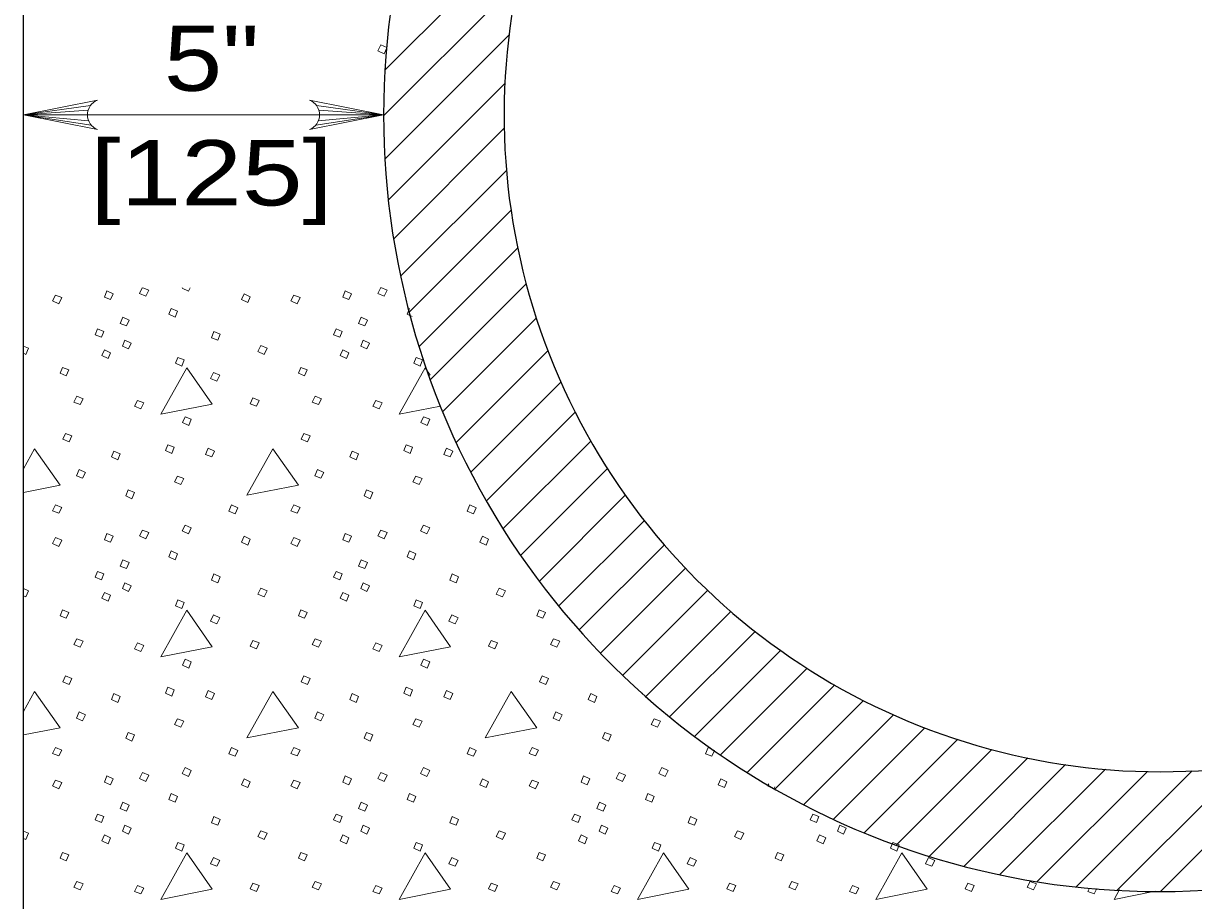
# Model space of a CAD drawing. Extents: x 1036.7 to 1070.7, y 883.9 to 905.9.
# Drawn here: x 1051.372 to 1054.169, y 894.74 to 896.836 of the extents above; entities that cross this region are included whole.
import ezdxf
from ezdxf.enums import TextEntityAlignment as Align

# ---------------------------------------------------------------- set-up
doc = ezdxf.new("R2010")
doc.units = 0
doc.header["$LTSCALE"] = 0.062
doc.layers.add('1', color=7, linetype='Continuous', lineweight=13)

msp = doc.modelspace()

# ---------------------------------------------------------------- linework, layer by layer
at = {"layer": '1'}
for p, q in [((1052.237, 896.72492), (1052.59142, 897.07925)), ((1052.23392, 896.61575), (1052.55467, 896.9365)), ((1052.23683, 896.51275), (1052.53375, 896.80967)), ((1052.22642, 896.78475), (1052.24092, 896.77892)), ((1052.245, 896.41483), (1052.5235, 896.69342)), ((1051.53242, 896.64), (1051.37217, 896.61758)), ((1051.527, 896.62892), (1051.37217, 896.61758)), ((1052.07292, 896.64), (1052.23317, 896.61758)), ((1052.07833, 896.62892), (1052.23317, 896.61758)), ((1052.07692, 896.61758), (1051.37217, 896.61758)), ((1051.52533, 896.61758), (1051.37217, 896.61758)), ((1051.52817, 896.60325), (1051.37217, 896.61758)), ((1051.53433, 896.59283), (1051.37217, 896.61758)), ((1052.23317, 896.61758), (1051.96858, 896.61758)), ((1052.071, 896.59283), (1052.23317, 896.61758)), ((1052.07717, 896.60325), (1052.23317, 896.61758)), ((1052.08, 896.61758), (1052.23317, 896.61758)), ((1052.25742, 896.32142), (1052.52175, 896.58567)), ((1052.27392, 896.23183), (1052.52692, 896.48475)), ((1052.29417, 896.14617), (1052.53792, 896.38975)), ((1052.31817, 896.06408), (1052.55392, 896.29983)), ((1052.34508, 895.985), (1052.57433, 896.21417)), ((1052.29533, 896.15517), (1052.29542, 896.15508)), ((1052.37467, 895.9085), (1052.59867, 896.1325)), ((1052.40667, 895.8345), (1052.62642, 896.05425)), ((1052.34467, 895.99567), (1052.33233, 896.01325)), ((1052.44175, 895.76358), (1052.65742, 895.97925)), ((1052.47942, 895.69525), (1052.69142, 895.90725)), ((1051.39875, 895.81933), (1051.37217, 895.77175)), ((1052.51917, 895.62892), (1052.72825, 895.83808)), ((1052.56083, 895.56467), (1052.76858, 895.77233)), ((1052.6055, 895.50333), (1052.81142, 895.70925)), ((1052.65225, 895.44408), (1052.85667, 895.6485)), ((1052.70075, 895.38658), (1052.90442, 895.59017)), ((1052.75158, 895.33133), (1052.95475, 895.5345)), ((1052.80483, 895.27867), (1053.008, 895.48175)), ((1052.86, 895.22775), (1053.06367, 895.43142)), ((1052.917, 895.17867), (1053.12167, 895.38333)), ((1052.97683, 895.13258), (1053.18192, 895.33758)), ((1053.03867, 895.08842), (1053.24558, 895.29533)), ((1051.39875, 895.23967), (1051.37217, 895.19208)), ((1053.1025, 895.04608), (1053.31175, 895.2555)), ((1053.16858, 895.00633), (1053.38067, 895.21833)), ((1053.23758, 894.96925), (1053.45233, 895.184)), ((1053.30875, 894.93442), (1053.527, 895.15267)), ((1053.38225, 894.90192), (1053.60533, 895.125)), ((1053.45858, 894.87217), (1053.68733, 895.101)), ((1053.53817, 894.84583), (1053.77325, 895.08083)), ((1053.62083, 894.82242), (1053.86333, 895.065)), ((1054.09, 894.7615), (1054.40967, 895.08117)), ((1053.7065, 894.80217), (1053.9585, 895.054)), ((1053.79583, 894.78542), (1054.05917, 895.04875)), ((1053.88908, 894.77267), (1054.16633, 895.04983)), ((1053.987, 894.7645), (1054.28267, 895.06017))]:
    msp.add_line(p, q, dxfattribs=at)
at = {"layer": '1', "lineweight": 25}
msp.add_lwpolyline([(1051.37217, 893.80992), (1051.37217, 899.32858), (1051.9695, 899.32858), (1051.9695, 900.49317)], dxfattribs=at)
at = {"layer": '1'}
for points in [[(1052.24092, 896.77775), (1052.23442, 896.76375), (1052.21942, 896.77075), (1052.22642, 896.78475)], [(1051.54917, 896.58225), (1051.37217, 896.61758), (1051.54917, 896.653)], [(1052.05617, 896.58225), (1052.23317, 896.61758), (1052.05617, 896.653)], [(1051.65792, 896.20458), (1051.67167, 896.19908), (1051.66467, 896.18408), (1051.64967, 896.19108), (1051.65642, 896.20458)], [(1051.77083, 896.20458), (1051.76658, 896.19608), (1051.75158, 896.20308), (1051.75233, 896.20458)], [(1052.3015, 896.1355), (1052.28933, 896.14117), (1052.29533, 896.15517)], [(1051.37217, 896.06517), (1051.38475, 896.06017), (1051.37775, 896.04517), (1051.37217, 896.04775)], [(1052.33233, 896.01325), (1052.27033, 895.90225), (1052.36958, 895.92158)], [(1051.37217, 895.71533), (1051.45975, 895.73242), (1051.39875, 895.81933)], [(1051.37217, 895.4855), (1051.38475, 895.4805), (1051.37775, 895.4655), (1051.37217, 895.46808)], [(1051.37217, 895.13567), (1051.45975, 895.15275), (1051.39875, 895.23967)], [(1052.85233, 895.23508), (1052.85108, 895.23567), (1052.85133, 895.23617)], [(1053.16817, 895.01167), (1053.16592, 895.00683), (1053.15092, 895.01383), (1053.15367, 895.01925)], [(1051.37217, 894.90583), (1051.38475, 894.90083), (1051.37775, 894.88583), (1051.37217, 894.88842)], [(1053.938, 894.76875), (1053.93158, 894.75592), (1053.91658, 894.76192), (1053.92042, 894.76958)], [(1053.99258, 894.76617), (1053.97958, 894.74292), (1054.07733, 894.76208)]]:
    msp.add_lwpolyline(points, dxfattribs=at)
for points in [[(1051.44875, 896.18708), (1051.46375, 896.18108), (1051.45675, 896.16617), (1051.44175, 896.17317)], [(1051.57167, 896.19708), (1051.58667, 896.19008), (1051.58067, 896.17617), (1051.56567, 896.18208)], [(1051.8995, 896.19008), (1051.9145, 896.18308), (1051.9085, 896.16917), (1051.8935, 896.17617)], [(1052.0185, 896.18708), (1052.0335, 896.18108), (1052.0265, 896.16617), (1052.0115, 896.17317)], [(1052.14142, 896.19708), (1052.15642, 896.19008), (1052.15042, 896.17617), (1052.13542, 896.18208)], [(1052.22642, 896.20508), (1052.24142, 896.19908), (1052.23442, 896.18408), (1052.21942, 896.19108)], [(1051.72558, 896.15517), (1051.74058, 896.14817), (1051.73458, 896.13417), (1051.71958, 896.14117)], [(1051.60967, 896.13417), (1051.62467, 896.12717), (1051.61867, 896.11317), (1051.60367, 896.11917)], [(1052.17942, 896.13417), (1052.19442, 896.12717), (1052.18842, 896.11317), (1052.17342, 896.11917)], [(1051.54967, 896.10617), (1051.56467, 896.10017), (1051.55867, 896.08617), (1051.54367, 896.09217)], [(1051.82758, 896.10017), (1051.84258, 896.09317), (1051.83658, 896.07917), (1051.82158, 896.08517)], [(1052.11942, 896.10617), (1052.13442, 896.10017), (1052.12842, 896.08617), (1052.11342, 896.09217)], [(1051.61467, 896.07917), (1051.62967, 896.07217), (1051.62367, 896.05817), (1051.60867, 896.06517)], [(1052.18442, 896.07917), (1052.19942, 896.07217), (1052.19342, 896.05817), (1052.17842, 896.06517)], [(1051.56567, 896.05617), (1051.58067, 896.04917), (1051.57467, 896.03517), (1051.55967, 896.04217)], [(1051.9395, 896.06617), (1051.9545, 896.06017), (1051.9475, 896.04517), (1051.9325, 896.05217)], [(1052.13542, 896.05617), (1052.15042, 896.04917), (1052.14442, 896.03517), (1052.12942, 896.04217)], [(1051.46575, 896.01425), (1051.48075, 896.00825), (1051.47475, 895.99425), (1051.45975, 896.00025)], [(1051.74158, 896.03817), (1051.75658, 896.03225), (1051.75058, 896.01725), (1051.73558, 896.02425)], [(1052.0355, 896.01425), (1052.0505, 896.00825), (1052.0445, 895.99425), (1052.0295, 896.00025)], [(1052.31133, 896.03817), (1052.32633, 896.03225), (1052.32033, 896.01725), (1052.30533, 896.02425)], [(1051.76258, 896.01325), (1051.70067, 895.90225), (1051.82358, 895.92625)], [(1051.82658, 896.00225), (1051.84158, 895.99525), (1051.83458, 895.98125), (1051.81958, 895.98725)], [(1051.49975, 895.94525), (1051.51475, 895.93925), (1051.50775, 895.92525), (1051.49275, 895.93125)], [(1051.64467, 895.93525), (1051.65967, 895.92925), (1051.65267, 895.91525), (1051.63767, 895.92125)], [(1051.9205, 895.94125), (1051.9355, 895.93525), (1051.9295, 895.92125), (1051.9145, 895.92725)], [(1052.0695, 895.94525), (1052.08442, 895.93925), (1052.07742, 895.92525), (1052.0625, 895.93125)], [(1052.21442, 895.93525), (1052.22942, 895.92925), (1052.22242, 895.91525), (1052.20742, 895.92125)], [(1051.75858, 895.89625), (1051.77358, 895.89033), (1051.76758, 895.87533), (1051.75258, 895.88233)], [(1052.32833, 895.89625), (1052.34333, 895.89033), (1052.33733, 895.87533), (1052.32233, 895.88233)], [(1051.47275, 895.85633), (1051.48775, 895.85033), (1051.48175, 895.83633), (1051.46675, 895.84233)], [(1052.0425, 895.85633), (1052.0575, 895.85033), (1052.0515, 895.83633), (1052.0365, 895.84233)], [(1051.71758, 895.82933), (1051.73258, 895.82333), (1051.72658, 895.80833), (1051.71167, 895.81533)], [(1051.81358, 895.82133), (1051.82858, 895.81433), (1051.82258, 895.80033), (1051.80758, 895.80633)], [(1051.9685, 895.81933), (1051.9065, 895.70842), (1052.0295, 895.73242)], [(1052.28733, 895.82933), (1052.30233, 895.82333), (1052.29633, 895.80833), (1052.28133, 895.81533)], [(1052.38333, 895.82133), (1052.39833, 895.81433), (1052.39233, 895.80033), (1052.37733, 895.80633)], [(1051.58867, 895.81433), (1051.60367, 895.80733), (1051.59767, 895.79333), (1051.58267, 895.80033)], [(1052.15842, 895.81433), (1052.17342, 895.80733), (1052.16742, 895.79333), (1052.15242, 895.80033)], [(1051.50575, 895.77033), (1051.52075, 895.76333), (1051.51375, 895.74933), (1051.49875, 895.75533)], [(1052.07542, 895.77033), (1052.09042, 895.76333), (1052.08342, 895.74933), (1052.0685, 895.75533)], [(1051.74058, 895.75433), (1051.75558, 895.74833), (1051.74858, 895.73442), (1051.73358, 895.74042)], [(1052.31033, 895.75433), (1052.32533, 895.74833), (1052.31833, 895.73442), (1052.30333, 895.74042)], [(1051.62267, 895.72142), (1051.63767, 895.71542), (1051.63167, 895.70042), (1051.61667, 895.70742)], [(1052.19242, 895.72142), (1052.20742, 895.71542), (1052.20142, 895.70042), (1052.18642, 895.70742)], [(1051.44875, 895.68542), (1051.46375, 895.67942), (1051.45675, 895.66542), (1051.44175, 895.67142)], [(1051.86958, 895.68542), (1051.88458, 895.67842), (1051.87858, 895.66442), (1051.86358, 895.67042)], [(1052.0185, 895.68542), (1052.0335, 895.67942), (1052.0265, 895.66542), (1052.0115, 895.67142)], [(1052.43925, 895.68542), (1052.45425, 895.67842), (1052.44825, 895.66442), (1052.43325, 895.67042)], [(1051.65667, 895.62542), (1051.67167, 895.61942), (1051.66467, 895.60442), (1051.64967, 895.61142)], [(1051.75858, 895.63742), (1051.77358, 895.63042), (1051.76658, 895.61642), (1051.75158, 895.62342)], [(1052.22642, 895.62542), (1052.24142, 895.61942), (1052.23442, 895.60442), (1052.21942, 895.61142)], [(1052.32833, 895.63742), (1052.34333, 895.63042), (1052.33633, 895.61642), (1052.32133, 895.62342)], [(1051.44875, 895.60742), (1051.46375, 895.60142), (1051.45675, 895.5865), (1051.44175, 895.5935)], [(1051.57167, 895.61742), (1051.58667, 895.61042), (1051.58067, 895.5965), (1051.56567, 895.60242)], [(1051.8995, 895.61042), (1051.9145, 895.60342), (1051.9085, 895.5895), (1051.8935, 895.5965)], [(1052.0185, 895.60742), (1052.0335, 895.60142), (1052.0265, 895.5865), (1052.0115, 895.5935)], [(1052.14142, 895.61742), (1052.15642, 895.61042), (1052.15042, 895.5965), (1052.13542, 895.60242)], [(1052.46925, 895.61042), (1052.48425, 895.60342), (1052.47825, 895.5895), (1052.46325, 895.5965)], [(1051.72558, 895.5755), (1051.74058, 895.5685), (1051.73458, 895.5545), (1051.71958, 895.5615)], [(1052.29533, 895.5755), (1052.31033, 895.5685), (1052.30433, 895.5545), (1052.28933, 895.5615)], [(1051.60967, 895.5545), (1051.62467, 895.5475), (1051.61867, 895.5335), (1051.60367, 895.5395)], [(1052.17942, 895.5545), (1052.19442, 895.5475), (1052.18842, 895.5335), (1052.17342, 895.5395)], [(1051.54967, 895.5265), (1051.56467, 895.5205), (1051.55867, 895.5065), (1051.54367, 895.5125)], [(1051.82758, 895.5205), (1051.84258, 895.5135), (1051.83658, 895.4995), (1051.82158, 895.5055)], [(1052.11942, 895.5265), (1052.13442, 895.5205), (1052.12842, 895.5065), (1052.11342, 895.5125)], [(1052.39733, 895.5205), (1052.41233, 895.5135), (1052.40633, 895.4995), (1052.39133, 895.5055)], [(1051.61467, 895.4995), (1051.62967, 895.4925), (1051.62367, 895.4785), (1051.60867, 895.4855)], [(1051.9395, 895.4865), (1051.9545, 895.4805), (1051.9475, 895.4655), (1051.9325, 895.4725)], [(1052.18442, 895.4995), (1052.19942, 895.4925), (1052.19342, 895.4785), (1052.17842, 895.4855)], [(1052.50925, 895.4865), (1052.52425, 895.4805), (1052.51725, 895.4655), (1052.50225, 895.4725)], [(1051.56567, 895.4765), (1051.58067, 895.4695), (1051.57467, 895.4555), (1051.55967, 895.4625)], [(1051.74158, 895.4585), (1051.75658, 895.45258), (1051.75058, 895.43758), (1051.73558, 895.44458)], [(1052.13542, 895.4765), (1052.15042, 895.4695), (1052.14442, 895.4555), (1052.12942, 895.4625)], [(1052.31133, 895.4585), (1052.32633, 895.45258), (1052.32033, 895.43758), (1052.30533, 895.44458)], [(1051.46575, 895.43458), (1051.48075, 895.42858), (1051.47475, 895.41458), (1051.45975, 895.42058)], [(1051.76258, 895.43358), (1051.70067, 895.32258), (1051.82358, 895.34658)], [(1052.0355, 895.43458), (1052.0505, 895.42858), (1052.0445, 895.41458), (1052.0295, 895.42058)], [(1052.33233, 895.43358), (1052.27033, 895.32258), (1052.39333, 895.34658)], [(1052.60517, 895.43458), (1052.62017, 895.42858), (1052.61417, 895.41458), (1052.59917, 895.42058)], [(1051.82658, 895.42258), (1051.84158, 895.41558), (1051.83458, 895.40158), (1051.81958, 895.40758)], [(1052.39633, 895.42258), (1052.41133, 895.41558), (1052.40433, 895.40158), (1052.38933, 895.40758)], [(1051.49975, 895.36558), (1051.51475, 895.35958), (1051.50775, 895.34558), (1051.49275, 895.35158)], [(1051.64467, 895.35558), (1051.65967, 895.34958), (1051.65267, 895.33558), (1051.63767, 895.34158)], [(1051.9205, 895.36158), (1051.9355, 895.35558), (1051.9295, 895.34158), (1051.9145, 895.34758)], [(1052.0695, 895.36558), (1052.08442, 895.35958), (1052.07742, 895.34558), (1052.0625, 895.35158)], [(1052.21442, 895.35558), (1052.22942, 895.34958), (1052.22242, 895.33558), (1052.20742, 895.34158)], [(1052.49025, 895.36158), (1052.50525, 895.35558), (1052.49925, 895.34158), (1052.48425, 895.34758)], [(1052.63917, 895.36558), (1052.65417, 895.35958), (1052.64717, 895.34558), (1052.63217, 895.35158)], [(1051.75858, 895.31658), (1051.77358, 895.31058), (1051.76758, 895.29567), (1051.75258, 895.30267)], [(1052.32833, 895.31658), (1052.34333, 895.31058), (1052.33733, 895.29567), (1052.32233, 895.30267)], [(1051.47275, 895.27667), (1051.48775, 895.27067), (1051.48175, 895.25667), (1051.46675, 895.26267)], [(1052.0425, 895.27667), (1052.0575, 895.27067), (1052.0515, 895.25667), (1052.0365, 895.26267)], [(1052.61217, 895.27667), (1052.62717, 895.27067), (1052.62117, 895.25667), (1052.60617, 895.26267)], [(1051.58867, 895.23467), (1051.60367, 895.22767), (1051.59767, 895.21367), (1051.58267, 895.22067)], [(1051.71758, 895.24967), (1051.73258, 895.24367), (1051.72658, 895.22867), (1051.71167, 895.23567)], [(1051.81358, 895.24167), (1051.82858, 895.23467), (1051.82258, 895.22067), (1051.80758, 895.22667)], [(1051.9685, 895.23967), (1051.9065, 895.12875), (1052.0295, 895.15275)], [(1052.15842, 895.23467), (1052.17342, 895.22767), (1052.16742, 895.21367), (1052.15242, 895.22067)], [(1052.28733, 895.24967), (1052.30233, 895.24367), (1052.29633, 895.22867), (1052.28133, 895.23567)], [(1052.38333, 895.24167), (1052.39833, 895.23467), (1052.39233, 895.22067), (1052.37733, 895.22667)], [(1052.53825, 895.23967), (1052.47625, 895.12875), (1052.59917, 895.15275)], [(1052.72817, 895.23467), (1052.74317, 895.22767), (1052.73717, 895.21367), (1052.72217, 895.22067)], [(1051.50575, 895.19067), (1051.52075, 895.18367), (1051.51375, 895.16967), (1051.49875, 895.17567)], [(1051.74058, 895.17467), (1051.75558, 895.16867), (1051.74858, 895.15475), (1051.73358, 895.16075)], [(1052.07542, 895.19067), (1052.09042, 895.18367), (1052.08342, 895.16967), (1052.0685, 895.17567)], [(1052.31033, 895.17467), (1052.32533, 895.16867), (1052.31833, 895.15475), (1052.30333, 895.16075)], [(1052.64517, 895.19067), (1052.66017, 895.18367), (1052.65317, 895.16967), (1052.63817, 895.17567)], [(1052.88008, 895.17467), (1052.89508, 895.16867), (1052.88808, 895.15475), (1052.87308, 895.16075)], [(1051.62267, 895.14175), (1051.63767, 895.13575), (1051.63167, 895.12075), (1051.61667, 895.12775)], [(1052.19242, 895.14175), (1052.20742, 895.13575), (1052.20142, 895.12075), (1052.18642, 895.12775)], [(1052.76217, 895.14175), (1052.77708, 895.13575), (1052.77117, 895.12075), (1052.75617, 895.12775)], [(1051.44875, 895.10575), (1051.46375, 895.09975), (1051.45675, 895.08575), (1051.44175, 895.09175)], [(1051.86958, 895.10575), (1051.88458, 895.09875), (1051.87858, 895.08475), (1051.86358, 895.09075)], [(1052.0185, 895.10575), (1052.0335, 895.09975), (1052.0265, 895.08575), (1052.0115, 895.09175)], [(1052.43925, 895.10575), (1052.45425, 895.09875), (1052.44825, 895.08475), (1052.43325, 895.09075)], [(1052.58825, 895.10575), (1052.60317, 895.09975), (1052.59625, 895.08575), (1052.58125, 895.09175)], [(1053.009, 895.10575), (1053.024, 895.09875), (1053.018, 895.08475), (1053.003, 895.09075)], [(1051.57167, 895.03775), (1051.58667, 895.03075), (1051.58067, 895.01683), (1051.56567, 895.02275)], [(1051.65667, 895.04575), (1051.67167, 895.03975), (1051.66467, 895.02475), (1051.64967, 895.03175)], [(1051.75858, 895.05775), (1051.77358, 895.05075), (1051.76658, 895.03675), (1051.75158, 895.04375)], [(1052.14142, 895.03775), (1052.15642, 895.03075), (1052.15042, 895.01683), (1052.13542, 895.02275)], [(1052.22642, 895.04575), (1052.24142, 895.03975), (1052.23442, 895.02475), (1052.21942, 895.03175)], [(1052.32833, 895.05775), (1052.34333, 895.05075), (1052.33633, 895.03675), (1052.32133, 895.04375)], [(1052.71117, 895.03775), (1052.72617, 895.03075), (1052.72017, 895.01683), (1052.70517, 895.02275)], [(1052.79608, 895.04575), (1052.81108, 895.03975), (1052.80408, 895.02475), (1052.78908, 895.03175)], [(1052.89808, 895.05775), (1052.91308, 895.05075), (1052.90608, 895.03675), (1052.89108, 895.04375)], [(1051.44875, 895.02775), (1051.46375, 895.02183), (1051.45675, 895.00683), (1051.44175, 895.01383)], [(1051.8995, 895.03075), (1051.9145, 895.02375), (1051.9085, 895.00983), (1051.8935, 895.01683)], [(1052.0185, 895.02775), (1052.0335, 895.02183), (1052.0265, 895.00683), (1052.0115, 895.01383)], [(1052.46925, 895.03075), (1052.48425, 895.02375), (1052.47825, 895.00983), (1052.46325, 895.01683)], [(1052.58825, 895.02775), (1052.60317, 895.02183), (1052.59625, 895.00683), (1052.58125, 895.01383)], [(1053.039, 895.03075), (1053.054, 895.02375), (1053.048, 895.00983), (1053.033, 895.01683)], [(1051.72558, 894.99583), (1051.74058, 894.98883), (1051.73458, 894.97483), (1051.71958, 894.98183)], [(1052.29533, 894.99583), (1052.31033, 894.98883), (1052.30433, 894.97483), (1052.28933, 894.98183)], [(1052.86508, 894.99583), (1052.88008, 894.98883), (1052.87408, 894.97483), (1052.85908, 894.98183)], [(1051.60967, 894.97483), (1051.62467, 894.96783), (1051.61867, 894.95383), (1051.60367, 894.95983)], [(1052.17942, 894.97483), (1052.19442, 894.96783), (1052.18842, 894.95383), (1052.17342, 894.95983)], [(1052.74917, 894.97483), (1052.76417, 894.96783), (1052.75817, 894.95383), (1052.74317, 894.95983)], [(1051.54967, 894.94683), (1051.56467, 894.94083), (1051.55867, 894.92683), (1051.54367, 894.93283)], [(1051.82758, 894.94083), (1051.84258, 894.93383), (1051.83658, 894.91983), (1051.82158, 894.92583)], [(1052.11942, 894.94683), (1052.13442, 894.94083), (1052.12842, 894.92683), (1052.11342, 894.93283)], [(1052.39733, 894.94083), (1052.41233, 894.93383), (1052.40633, 894.91983), (1052.39133, 894.92583)], [(1052.68917, 894.94683), (1052.70417, 894.94083), (1052.69817, 894.92683), (1052.68317, 894.93283)], [(1052.967, 894.94083), (1052.982, 894.93383), (1052.976, 894.91983), (1052.961, 894.92583)], [(1053.25892, 894.94683), (1053.27392, 894.94083), (1053.26792, 894.92683), (1053.25292, 894.93283)], [(1051.56567, 894.89683), (1051.58067, 894.88983), (1051.57467, 894.87583), (1051.55967, 894.88283)], [(1051.61467, 894.91983), (1051.62967, 894.91283), (1051.62367, 894.89883), (1051.60867, 894.90583)], [(1051.9395, 894.90683), (1051.9545, 894.90083), (1051.9475, 894.88583), (1051.9325, 894.89283)], [(1052.13542, 894.89683), (1052.15042, 894.88983), (1052.14442, 894.87583), (1052.12942, 894.88283)], [(1052.18442, 894.91983), (1052.19942, 894.91283), (1052.19342, 894.89883), (1052.17842, 894.90583)], [(1052.50925, 894.90683), (1052.52425, 894.90083), (1052.51725, 894.88583), (1052.50225, 894.89283)], [(1052.70517, 894.89683), (1052.72017, 894.88983), (1052.71417, 894.87583), (1052.69917, 894.88283)], [(1052.75417, 894.91983), (1052.76917, 894.91283), (1052.76317, 894.89883), (1052.74817, 894.90583)], [(1053.079, 894.90683), (1053.094, 894.90083), (1053.087, 894.88583), (1053.072, 894.89283)], [(1053.27492, 894.89683), (1053.28992, 894.88983), (1053.28392, 894.87583), (1053.26892, 894.88283)], [(1053.32383, 894.91983), (1053.33883, 894.91283), (1053.33283, 894.89883), (1053.31783, 894.90583)], [(1051.74158, 894.87883), (1051.75658, 894.87292), (1051.75058, 894.85792), (1051.73558, 894.86492)], [(1052.31133, 894.87883), (1052.32633, 894.87292), (1052.32033, 894.85792), (1052.30533, 894.86492)], [(1052.88108, 894.87883), (1052.89608, 894.87292), (1052.89008, 894.85792), (1052.87508, 894.86492)], [(1053.45083, 894.87883), (1053.46583, 894.87292), (1053.45983, 894.85792), (1053.44483, 894.86492)], [(1051.46575, 894.85492), (1051.48075, 894.84892), (1051.47475, 894.83492), (1051.45975, 894.84092)], [(1051.76258, 894.85392), (1051.70067, 894.74292), (1051.82358, 894.76692)], [(1051.82658, 894.84292), (1051.84158, 894.83592), (1051.83458, 894.82192), (1051.81958, 894.82792)], [(1052.0355, 894.85492), (1052.0505, 894.84892), (1052.0445, 894.83492), (1052.0295, 894.84092)], [(1052.33233, 894.85392), (1052.27033, 894.74292), (1052.39333, 894.76692)], [(1052.39633, 894.84292), (1052.41133, 894.83592), (1052.40433, 894.82192), (1052.38933, 894.82792)], [(1052.60517, 894.85492), (1052.62017, 894.84892), (1052.61417, 894.83492), (1052.59917, 894.84092)], [(1052.90208, 894.85392), (1052.84008, 894.74292), (1052.963, 894.76692)], [(1052.966, 894.84292), (1052.981, 894.83592), (1052.974, 894.82192), (1052.959, 894.82792)], [(1053.17492, 894.85492), (1053.18992, 894.84892), (1053.18392, 894.83492), (1053.16892, 894.84092)], [(1053.47183, 894.85392), (1053.40983, 894.74292), (1053.53275, 894.76692)], [(1053.53575, 894.84292), (1053.55075, 894.83592), (1053.54375, 894.82192), (1053.52875, 894.82792)], [(1051.49975, 894.78592), (1051.51475, 894.77992), (1051.50775, 894.76592), (1051.49275, 894.77192)], [(1052.0695, 894.78592), (1052.08442, 894.77992), (1052.07742, 894.76592), (1052.0625, 894.77192)], [(1052.63917, 894.78592), (1052.65417, 894.77992), (1052.64717, 894.76592), (1052.63217, 894.77192)], [(1053.20892, 894.78592), (1053.22392, 894.77992), (1053.21692, 894.76592), (1053.20192, 894.77192)], [(1053.77867, 894.78592), (1053.79367, 894.77992), (1053.78667, 894.76592), (1053.77167, 894.77192)], [(1051.64467, 894.77592), (1051.65967, 894.76992), (1051.65267, 894.75592), (1051.63767, 894.76192)], [(1051.9205, 894.78192), (1051.9355, 894.77592), (1051.9295, 894.76192), (1051.9145, 894.76792)], [(1052.21442, 894.77592), (1052.22942, 894.76992), (1052.22242, 894.75592), (1052.20742, 894.76192)], [(1052.49025, 894.78192), (1052.50525, 894.77592), (1052.49925, 894.76192), (1052.48425, 894.76792)], [(1052.78408, 894.77592), (1052.79908, 894.76992), (1052.79208, 894.75592), (1052.77708, 894.76192)], [(1053.06, 894.78192), (1053.075, 894.77592), (1053.069, 894.76192), (1053.054, 894.76792)], [(1053.35383, 894.77592), (1053.36883, 894.76992), (1053.36183, 894.75592), (1053.34683, 894.76192)], [(1053.62975, 894.78192), (1053.64475, 894.77592), (1053.63875, 894.76192), (1053.62375, 894.76792)]]:
    msp.add_lwpolyline(points, close=True, dxfattribs=at)
for centre, start, end in [((1051.5635, 896.61766), 112.08782, 247.91395), ((1052.04184, 896.61766), 292.08605, 67.91218)]:
    msp.add_arc(centre, 0.0382, start, end, dxfattribs=at)
at = {"layer": '1', "lineweight": 25}
for centre, major_axis, start_param, end_param in [((1054.08944, 896.61762), (1.8563, 0), 2.2655043, 4.7123821), ((1054.08944, 896.61762), (1.8563, 0), 4.7123821, 7.1267519), ((1054.09071, 896.61711), (1.56952, 0), 2.3177732, 4.7123633), ((1054.09071, 896.61711), (1.56952, 0), 4.7123633, 7.1023478)]:
    msp.add_ellipse(centre, major_axis=major_axis, ratio=0.999895, start_param=start_param, end_param=end_param, dxfattribs=at)

# ---------------------------------------------------------------- texts
at = {"layer": '1'}
for s, width, p in [('5"', 1.2, (1051.82212, 896.67517)), ('[125]', 1.25, (1051.82208, 896.40117))]:
    msp.add_text(s, height=0.156, dxfattribs=dict(at, width=width)).set_placement(p, align=Align.CENTER)

doc.saveas('drawing.dxf')
